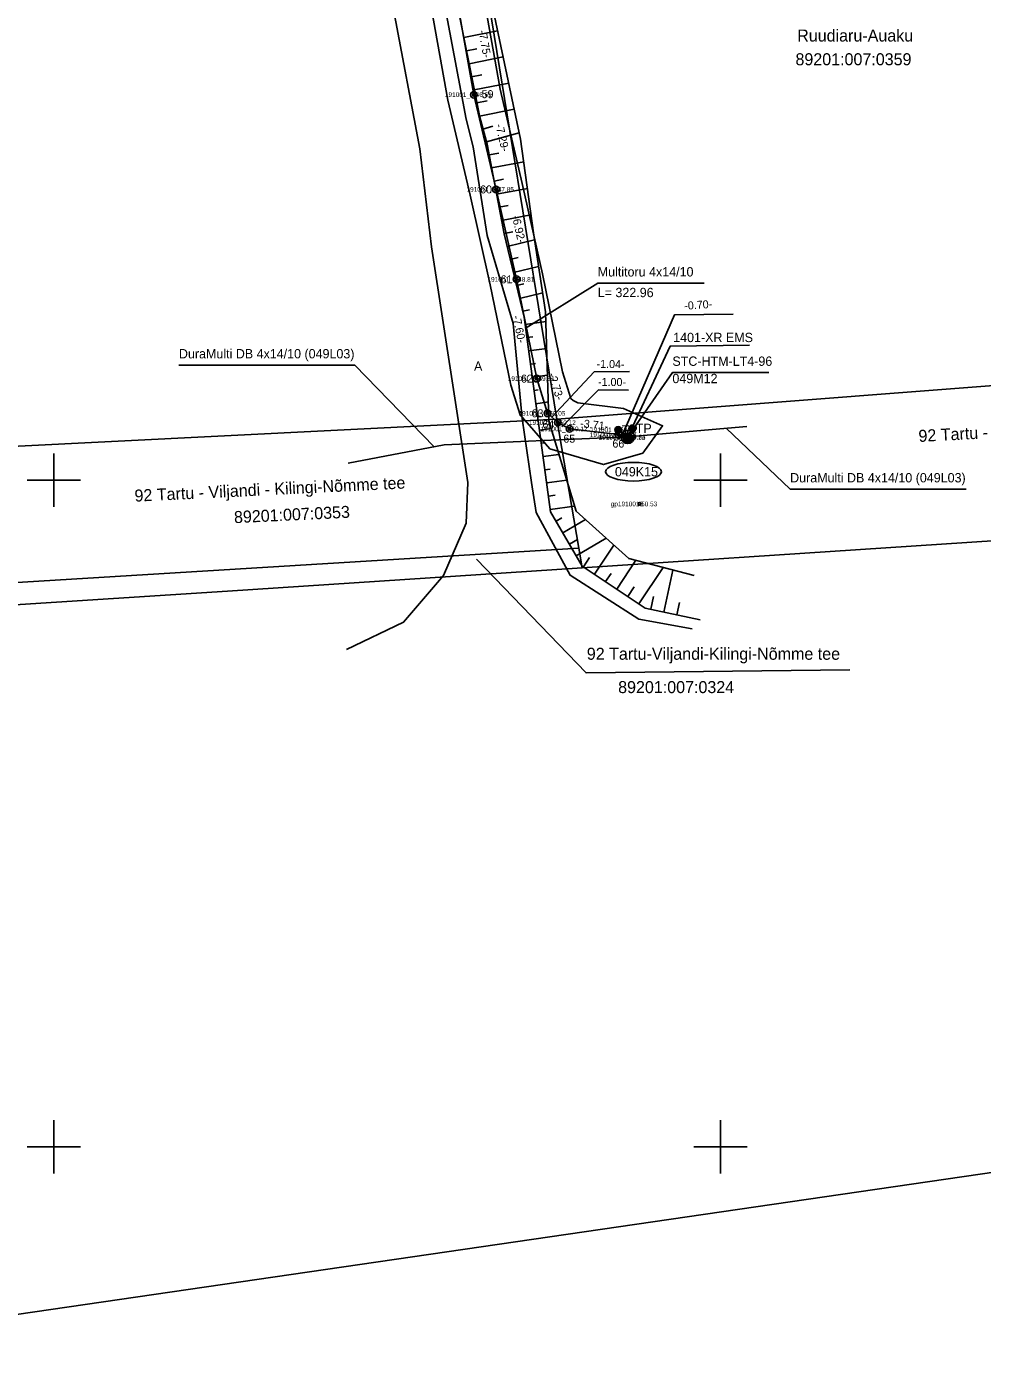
# Model space of a CAD drawing. Extents: x 604066 to 604956, y 6473634 to 6474346.
# Drawn here: x 604648 to 604719.6, y 6473633.8 to 6473734 of the extents above; entities that cross this region are included whole.
import ezdxf

# ---------------------------------------------------------------- set-up
doc = ezdxf.new("R2010")
doc.units = 0
for name, color, linetype in [('ABIJOONIS', 7, 'Continuous'), ('JOONSIDE', 7, 'Continuous'), ('KAEVUNR', 7, 'Continuous'), ('KOORDPUNKT', 7, 'Continuous'), ('MOOTKORG', 7, 'Continuous'), ('MOOTMPUNKT', 7, 'Continuous'), ('MOOTNR', 7, 'Continuous'), ('MOOTPIIR', 7, 'Continuous'), ('PIIR', 7, 'Continuous'), ('POST', 7, 'Continuous'), ('RELJEEF', 7, 'Continuous'), ('SIKAEV', 7, 'Continuous'), ('SITRASS', 7, 'Continuous'), ('TEE', 7, 'Continuous'), ('VORK', 7, 'Continuous'), ('VORMISTUS', 7, 'Continuous')]:
    doc.layers.add(name, color=color, linetype=linetype)

msp = doc.modelspace()

# ---------------------------------------------------------------- linework, layer by layer
at = {"layer": 'ABIJOONIS'}
msp.add_ellipse((604693.47, 6473700.63), major_axis=(2.1, 0), ratio=0.333333, dxfattribs=at)
at = {"layer": 'JOONSIDE'}
for points in [[(604692.63, 6473703.34), (604696.55, 6473712.4), (604700.95, 6473712.45)], [(604687.31, 6473704.69), (604690.51, 6473708.12), (604693.17, 6473708.14)], [(604688.09, 6473703.99), (604690.85, 6473706.78), (604693.09, 6473706.75)]]:
    msp.add_lwpolyline(points, dxfattribs=at)
at = {"layer": 'KOORDPUNKT'}
for centre, radius in [((604681.5, 6473728.9), 0.25), ((604681.5, 6473728.9), 0.025), ((604681.5, 6473728.9), 0.0221), ((604681.5, 6473728.9), 0.0161), ((604681.5, 6473728.9), 0.0191), ((604681.5, 6473728.9), 0.0132), ((604681.5, 6473728.9), 0.00726), ((604681.5, 6473728.9), 0.0102), ((604681.5, 6473728.9), 0.0043), ((604683.16, 6473721.8), 0.25), ((604683.16, 6473721.8), 0.025), ((604683.16, 6473721.8), 0.0221), ((604683.16, 6473721.8), 0.0161), ((604683.16, 6473721.8), 0.0191), ((604683.16, 6473721.8), 0.0132), ((604683.16, 6473721.8), 0.0043), ((604683.16, 6473721.8), 0.00726), ((604683.16, 6473721.8), 0.0102), ((604684.69, 6473715.06), 0.25), ((604684.69, 6473715.06), 0.025), ((604684.69, 6473715.06), 0.0191), ((604684.69, 6473715.06), 0.0221), ((604684.69, 6473715.06), 0.0161), ((604684.69, 6473715.06), 0.00726), ((604684.69, 6473715.06), 0.0102), ((604684.69, 6473715.06), 0.0132), ((604684.69, 6473715.06), 0.0043), ((604686.21, 6473707.61), 0.25), ((604686.21, 6473707.61), 0.025), ((604686.21, 6473707.61), 0.0161), ((604686.21, 6473707.61), 0.0191), ((604686.21, 6473707.61), 0.0221), ((604686.21, 6473707.61), 0.0132), ((604686.21, 6473707.61), 0.0043), ((604686.21, 6473707.61), 0.00726), ((604686.21, 6473707.61), 0.0102), ((604687.02, 6473705.01), 0.25), ((604687.02, 6473705.01), 0.025), ((604687.02, 6473705.01), 0.0161), ((604687.02, 6473705.01), 0.0191), ((604687.02, 6473705.01), 0.0221), ((604687.02, 6473705.01), 0.00726), ((604687.02, 6473705.01), 0.0102), ((604687.02, 6473705.01), 0.0132), ((604687.02, 6473705.01), 0.0043), ((604687.8, 6473704.32), 0.25), ((604687.8, 6473704.32), 0.0221), ((604687.8, 6473704.32), 0.025), ((604687.8, 6473704.32), 0.0191), ((604687.8, 6473704.32), 0.0132), ((604687.8, 6473704.32), 0.0161), ((604687.8, 6473704.32), 0.0102), ((604687.8, 6473704.32), 0.0043), ((604687.8, 6473704.32), 0.00726), ((604688.68, 6473703.84), 0.25), ((604688.68, 6473703.84), 0.0221), ((604688.68, 6473703.84), 0.025), ((604688.68, 6473703.84), 0.0132), ((604688.68, 6473703.84), 0.0161), ((604688.68, 6473703.84), 0.0191), ((604688.68, 6473703.84), 0.0102), ((604688.68, 6473703.84), 0.0043), ((604688.68, 6473703.84), 0.00726), ((604692.36, 6473703.41), 0.25), ((604692.36, 6473703.41), 0.0191), ((604692.36, 6473703.41), 0.0221), ((604692.36, 6473703.41), 0.025), ((604692.36, 6473703.41), 0.0102), ((604692.36, 6473703.41), 0.0132), ((604692.36, 6473703.41), 0.0161), ((604692.36, 6473703.41), 0.0043), ((604692.36, 6473703.41), 0.00726), ((604693.04, 6473703.24), 0.25), ((604693.04, 6473703.24), 0.025), ((604693.04, 6473703.24), 0.0191), ((604693.04, 6473703.24), 0.0221), ((604693.04, 6473703.24), 0.0161), ((604693.04, 6473703.24), 0.00726), ((604693.04, 6473703.24), 0.0102), ((604693.04, 6473703.24), 0.0132), ((604693.04, 6473703.24), 0.0043)]:
    msp.add_circle(centre, radius, dxfattribs=at)
at = {"layer": 'MOOTMPUNKT'}
for centre in [(604681.5, 6473728.9), (604683.16, 6473721.8), (604684.69, 6473715.06), (604686.21, 6473707.61), (604687.02, 6473705.01), (604687.8, 6473704.32), (604688.68, 6473703.84), (604692.33, 6473703.77), (604692.36, 6473703.41), (604693.04, 6473703.24), (604693.91, 6473698.22)]:
    msp.add_circle(centre, 0.1, dxfattribs=at)
at = {"layer": 'MOOTPIIR'}
msp.add_lwpolyline([(604678.17, 6473736.19), (604679.54, 6473728.5), (604681.21, 6473721.36), (604682.73, 6473714.64), (604684.27, 6473707.11), (604684.96, 6473704.89), (604687.2, 6473702.34), (604691.21, 6473701.16), (604694.16, 6473702.01), (604695.65, 6473704.08), (604692.72, 6473705.38), (604689.29, 6473705.79), (604688.95, 6473705.97), (604688.76, 6473706.13), (604688.15, 6473708.11), (604686.64, 6473715.48), (604685.11, 6473722.25), (604683.46, 6473729.31), (604682.11, 6473736.88)], dxfattribs=at)
at = {"layer": 'PIIR'}
for points in [[(604833.54, 6473909.5), (604897.39, 6473936.49), (604953.49, 6473960.24), (604956.07, 6473961.29), (604940.8, 6473724.06), (604687.73, 6473704.56), (604680.66, 6473747.8), (604821.94, 6473844.68)], [(604687.73, 6473704.56), (604940.8, 6473724.06), (604940.18, 6473714.53), (604940.07, 6473712.83), (604892.72, 6473708.69), (604839.74, 6473704.2), (604787.09, 6473700.12), (604735.18, 6473696.42), (604689.63, 6473693.43), (604689.38, 6473694.91)], [(604429.15, 6473679), (604428.82, 6473685.17), (604422.99, 6473691.29), (604687.73, 6473704.56), (604689.38, 6473694.91)], [(604429.15, 6473679), (604689.38, 6473694.91), (604689.63, 6473693.43), (604663.03, 6473691.68), (604611.7, 6473688.38), (604559, 6473685.22), (604513.61, 6473682.6), (604464, 6473679.51), (604429.23, 6473677.5)]]:
    msp.add_lwpolyline(points, close=True, dxfattribs=at)
for points in [[(604392.23, 6473874.61), (604414.7, 6473872.41), (604426.55, 6473871.03), (604444.65, 6473869.66), (604482.63, 6473866.81), (604486.98, 6473866.41), (604549.55, 6473854.82), (604575.16, 6473852.02), (604645.55, 6473867.92), (604659, 6473875.69), (604714.62, 6473889.17), (604776, 6473903.81), (604824.84, 6473905.94), (604833.54, 6473909.5), (604821.94, 6473844.68), (604680.66, 6473747.8), (604687.73, 6473704.56), (604422.99, 6473691.29), (604421.99, 6473694.09), (604395.15, 6473723.9)], [(604681.7, 6473694.08), (604689.92, 6473685.54), (604709.7, 6473685.77)]]:
    msp.add_lwpolyline(points, dxfattribs=at)
at = {"layer": 'POST'}
for centre, radius in [((604692.33, 6473703.77), 0.25), ((604692.33, 6473703.77), 0.225), ((604692.33, 6473703.77), 0.2), ((604693.38, 6473703.88), 0.25), ((604693.38, 6473703.88), 0.225), ((604693.38, 6473703.88), 0.2), ((604693.38, 6473703.88), 0.175), ((604693.38, 6473703.88), 0.15), ((604693.38, 6473703.88), 0.125), ((604693.38, 6473703.88), 0.1), ((604693.38, 6473703.88), 0.075), ((604692.33, 6473703.77), 0.175), ((604692.33, 6473703.77), 0.15), ((604692.33, 6473703.77), 0.125), ((604692.33, 6473703.77), 0.1), ((604692.33, 6473703.77), 0.075), ((604692.33, 6473703.77), 0.05), ((604692.33, 6473703.77), 0.025), ((604693.38, 6473703.88), 0.05), ((604693.38, 6473703.88), 0.025)]:
    msp.add_circle(centre, radius, dxfattribs=at)
at = {"layer": 'RELJEEF'}
for p, q in [((604680.75, 6473733.18), (604683.28, 6473733.69)), ((604680.94, 6473732.2), (604681.71, 6473732.35)), ((604681.14, 6473731.22), (604683.7, 6473731.73)), ((604681.33, 6473730.24), (604682.1, 6473730.39)), ((604681.53, 6473729.26), (604684.11, 6473729.77)), ((604681.72, 6473728.28), (604682.5, 6473728.43)), ((604681.92, 6473727.3), (604684.53, 6473727.82)), ((604682.18, 6473726.33), (604682.93, 6473726.54)), ((604682.44, 6473725.37), (604684.9, 6473726.04)), ((604682.64, 6473724.39), (604683.38, 6473724.53)), ((604682.83, 6473723.41), (604685.24, 6473723.86)), ((604683.02, 6473722.42), (604683.72, 6473722.56)), ((604683.2, 6473721.44), (604685.51, 6473721.88)), ((604683.39, 6473720.46), (604684.06, 6473720.59)), ((604683.58, 6473719.48), (604685.78, 6473719.9)), ((604683.76, 6473718.49), (604684.41, 6473718.62)), ((604684, 6473717.52), (604686.04, 6473718.01)), ((604684.23, 6473716.55), (604684.82, 6473716.69)), ((604684.46, 6473715.58), (604686.35, 6473716.03)), ((604684.7, 6473714.6), (604685.24, 6473714.73)), ((604684.93, 6473713.63), (604686.66, 6473714.05)), ((604685.16, 6473712.66), (604685.66, 6473712.78)), ((604685.34, 6473711.68), (604686.91, 6473711.89)), ((604685.48, 6473710.69), (604685.91, 6473710.75)), ((604685.61, 6473709.69), (604686.97, 6473709.88)), ((604685.75, 6473708.7), (604686.12, 6473708.75)), ((604685.88, 6473707.71), (604687.03, 6473707.87)), ((604686.01, 6473706.72), (604686.33, 6473706.76)), ((604686.15, 6473705.73), (604687.09, 6473705.86)), ((604686.28, 6473704.74), (604686.53, 6473704.77)), ((604686.42, 6473703.75), (604687.3, 6473703.87)), ((604686.55, 6473702.76), (604686.86, 6473702.8)), ((604686.69, 6473701.77), (604687.88, 6473701.93)), ((604686.82, 6473700.78), (604687.23, 6473700.83)), ((604686.96, 6473699.79), (604688.46, 6473699.99)), ((604687.09, 6473698.8), (604687.59, 6473698.86)), ((604687.23, 6473697.8), (604689.04, 6473698.05)), ((604687.67, 6473696.92), (604688.1, 6473697.17)), ((604688.17, 6473696.05), (604689.86, 6473697.04)), ((604688.67, 6473695.19), (604689.27, 6473695.54)), ((604689.18, 6473694.33), (604691.43, 6473695.64)), ((604690.55, 6473692.94), (604692, 6473695.13)), ((604689.71, 6473693.49), (604690.17, 6473694.19)), ((604692.21, 6473691.83), (604693.65, 6473693.99)), ((604691.38, 6473692.39), (604691.79, 6473693.01)), ((604693.88, 6473690.73), (604695.69, 6473693.46)), ((604695.75, 6473690.11), (604696.43, 6473693.26)), ((604693.04, 6473691.28), (604693.53, 6473692.01)), ((604694.77, 6473690.32), (604694.98, 6473691.28)), ((604696.73, 6473689.9), (604696.93, 6473690.83))]:
    msp.add_line(p, q, dxfattribs=at)
for points in [[(604672.96, 6473774.44), (604673.75, 6473769.08), (604676.06, 6473758.37), (604677.74, 6473747.48), (604680.01, 6473736.85), (604681.94, 6473727.21), (604682.49, 6473725.19), (604683.77, 6473718.46), (604685.27, 6473712.22), (604687.25, 6473697.63), (604689.63, 6473693.55), (604694.35, 6473690.41), (604698.46, 6473689.52)], [(604674.27, 6473774.8), (604675.61, 6473769.86), (604677.36, 6473758.59), (604680.19, 6473748.09), (604682.49, 6473737.41), (604685, 6473725.57), (604685.96, 6473718.55), (604686.88, 6473712.63), (604687.13, 6473704.44), (604689.16, 6473697.67), (604693.13, 6473694.13), (604698.02, 6473692.84)]]:
    msp.add_lwpolyline(points, dxfattribs=at)
at = {"layer": 'SIKAEV'}
for p, q in [((604693.04, 6473703.24), (604692.62, 6473702.96)), ((604693.04, 6473703.74), (604693.04, 6473703.24)), ((604693.04, 6473703.24), (604693.45, 6473702.96))]:
    msp.add_line(p, q, dxfattribs=at)
msp.add_circle((604693.04, 6473703.24), 0.5, dxfattribs=at)
for radius in [0.475, 0.45, 0.425, 0.4, 0.375, 0.35, 0.325, 0.3, 0.275, 0.25, 0.225, 0.2, 0.175, 0.15, 0.125, 0.1, 0.075, 0.05]:
    msp.add_arc((604693.04, 6473703.24), radius, 213.5305, 326.4695, dxfattribs=at)
at = {"layer": 'SITRASS'}
for p, q in [((604693.04, 6473703.24), (604701.98, 6473704.02)), ((604692.45, 6473703.29), (604693.06, 6473703.51)), ((604692.45, 6473703.29), (604693.02, 6473702.97)), ((604692.45, 6473703.29), (604692.45, 6473703.29)), ((604692.48, 6473703.27), (604692.47, 6473703.3)), ((604692.52, 6473703.25), (604692.5, 6473703.3)), ((604692.56, 6473703.23), (604692.52, 6473703.31)), ((604692.59, 6473703.21), (604692.54, 6473703.32)), ((604692.79, 6473703.24), (604692.54, 6473703.24)), ((604692.63, 6473703.19), (604692.57, 6473703.33)), ((604692.66, 6473703.17), (604692.59, 6473703.34)), ((604692.7, 6473703.15), (604692.61, 6473703.35)), ((604692.73, 6473703.13), (604692.64, 6473703.36)), ((604692.77, 6473703.11), (604692.66, 6473703.36)), ((604692.8, 6473703.09), (604692.68, 6473703.37)), ((604692.86, 6473703.41), (604692.69, 6473703.59)), ((604692.86, 6473703.06), (604692.69, 6473702.88)), ((604692.84, 6473703.07), (604692.71, 6473703.38)), ((604692.87, 6473703.05), (604692.73, 6473703.39)), ((604692.91, 6473703.03), (604692.75, 6473703.4)), ((604692.95, 6473703.01), (604692.78, 6473703.41)), ((604692.98, 6473702.99), (604692.8, 6473703.42)), ((604693.02, 6473702.97), (604692.82, 6473703.43)), ((604693.04, 6473702.98), (604692.85, 6473703.43)), ((604693.06, 6473702.99), (604692.87, 6473703.44)), ((604693.09, 6473703), (604692.9, 6473703.45)), ((604693.11, 6473703), (604692.92, 6473703.46)), ((604693.13, 6473703.01), (604692.94, 6473703.47)), ((604693.16, 6473703.02), (604692.97, 6473703.48)), ((604693.18, 6473703.03), (604692.99, 6473703.49)), ((604693.21, 6473703.04), (604693.01, 6473703.49)), ((604693.63, 6473703.19), (604693.02, 6473702.97)), ((604693.04, 6473703.49), (604693.04, 6473703.74)), ((604693.23, 6473703.05), (604693.04, 6473703.5)), ((604693.04, 6473702.99), (604693.04, 6473702.74)), ((604693.63, 6473703.19), (604693.06, 6473703.51)), ((604693.25, 6473703.06), (604693.06, 6473703.51)), ((604693.28, 6473703.06), (604693.09, 6473703.49)), ((604693.3, 6473703.07), (604693.13, 6473703.47)), ((604693.32, 6473703.08), (604693.17, 6473703.45)), ((604693.35, 6473703.09), (604693.2, 6473703.43)), ((604693.22, 6473703.41), (604693.39, 6473703.59)), ((604693.22, 6473703.06), (604693.39, 6473702.88)), ((604693.37, 6473703.1), (604693.24, 6473703.41)), ((604693.39, 6473703.11), (604693.27, 6473703.39)), ((604693.29, 6473703.24), (604693.54, 6473703.24)), ((604693.42, 6473703.12), (604693.31, 6473703.37)), ((604693.44, 6473703.12), (604693.34, 6473703.35)), ((604693.46, 6473703.13), (604693.38, 6473703.34)), ((604693.49, 6473703.14), (604693.41, 6473703.32)), ((604693.51, 6473703.15), (604693.45, 6473703.3)), ((604693.53, 6473703.16), (604693.48, 6473703.28)), ((604693.56, 6473703.17), (604693.52, 6473703.26)), ((604693.58, 6473703.18), (604693.56, 6473703.24)), ((604693.6, 6473703.18), (604693.59, 6473703.22))]:
    msp.add_line(p, q, dxfattribs=at)
for points in [[(604680.14, 6473736.53), (604681.5, 6473728.9), (604683.16, 6473721.8), (604684.69, 6473715.06), (604686.21, 6473707.61), (604687.02, 6473705.01), (604687.8, 6473704.32), (604688.68, 6473703.84), (604692.36, 6473703.41), (604693.04, 6473703.24)], [(604685.43, 6473711.43), (604690.79, 6473714.77), (604698.77, 6473714.77)], [(604693.04, 6473703.24), (604696.21, 6473710.04), (604702.17, 6473710.13)], [(604678.51, 6473702.5), (604672.57, 6473708.63), (604659.38, 6473708.63)], [(604693.04, 6473703.24), (604696.39, 6473708.07), (604703.63, 6473708.07)], [(604693.04, 6473703.24), (604679.26, 6473702.64), (604672.06, 6473701.27)], [(604700.43, 6473703.89), (604705.22, 6473699.33), (604718.41, 6473699.33)]]:
    msp.add_lwpolyline(points, dxfattribs=at)
for radius in [0.25, 0.225, 0.2, 0.175, 0.15, 0.125, 0.1, 0.075, 0.05, 0.025]:
    msp.add_circle((604693.04, 6473703.24), radius, dxfattribs=at)
at = {"layer": 'TEE'}
for points in [[(604658.81, 6473832.59), (604663.41, 6473815.74), (604666.28, 6473803.94), (604668.26, 6473793.28), (604670.52, 6473784.17), (604671.08, 6473780.07), (604671.45, 6473778.51), (604672.22, 6473774.12), (604673.16, 6473768.83), (604674.71, 6473758.23), (604677.04, 6473747.39), (604679.12, 6473736.65), (604680.92, 6473727.06), (604681.45, 6473725), (604682.5, 6473718.34), (604684.44, 6473711.75), (604685.12, 6473704.62), (604685.81, 6473699.83), (604686.18, 6473697.57), (604688.71, 6473692.87), (604693.86, 6473689.57), (604697.87, 6473688.86)], [(604654.6, 6473831.66), (604658.7, 6473815.39), (604661.34, 6473804.07), (604663.57, 6473792.58), (604666.57, 6473778.33), (604668.53, 6473769.38), (604671.17, 6473757.48), (604673.52, 6473745.14), (604675.48, 6473735.29), (604677.45, 6473724.84), (604678.32, 6473717.49), (604681.05, 6473699.83), (604680.92, 6473696.77), (604679.22, 6473692.84), (604676.23, 6473689.35), (604671.94, 6473687.31)]]:
    msp.add_lwpolyline(points, dxfattribs=at)
at = {"layer": 'VORK'}
for p, q in [((604650, 6473702), (604650, 6473698)), ((604700, 6473702), (604700, 6473698)), ((604648, 6473700), (604652, 6473700)), ((604698, 6473700), (604702, 6473700)), ((604650, 6473652), (604650, 6473648)), ((604700, 6473652), (604700, 6473648)), ((604648, 6473650), (604652, 6473650)), ((604698, 6473650), (604702, 6473650))]:
    msp.add_line(p, q, dxfattribs=at)
at = {"layer": 'VORMISTUS'}
msp.add_lwpolyline([(604563.86, 6474037.6), (604705.86, 6474058.26), (604764.62, 6473654.52), (604622.61, 6473633.85)], close=True, dxfattribs=at)

# ---------------------------------------------------------------- texts
at = {"layer": 'JOONSIDE'}
for s, rotation, p in [('-7.75-', 280.1005, (604681.85, 6473733.69)), ('-7.29-', 283.1537, (604683.11, 6473726.64)), ('-6.92-', 282.7786, (604684.35, 6473719.78)), ('-0.70-', 3.9591, (604697.3, 6473712.77)), ('-7.60-', 281.5376, (604684.4, 6473712.29)), ('-1.04-', 359.2568, (604690.7, 6473708.42)), ('-2.73-', 287.3051, (604687.07, 6473707.94)), ('-1.00-', 359.4668, (604690.81, 6473707.07)), ('-3.71-', 353.2289, (604689.45, 6473703.98))]:
    msp.add_text(s, height=0.6, rotation=rotation, dxfattribs=at).set_placement(p)
at = {"layer": 'KAEVUNR'}
msp.add_text('049K15', height=0.7, dxfattribs=at).set_placement((604692.08, 6473700.28))
at = {"layer": 'KOORDPUNKT'}
for s, p in [('59 ', (604682.08, 6473728.64)), ('60 ', (604681.97, 6473721.5)), ('61 ', (604683.5, 6473714.76)), ('62 ', (604685.03, 6473707.31)), ('63 ', (604685.83, 6473704.71)), ('64 ', (604686.64, 6473703.89)), ('65 ', (604688.21, 6473702.81)), ('66 ', (604691.89, 6473702.44))]:
    msp.add_text(s, height=0.6, dxfattribs=at).set_placement(p)
at = {"layer": 'MOOTKORG'}
for s, p in [(' 46.61', (604681.5, 6473728.73)), (' 47.85', (604683.16, 6473721.63)), (' 48.81', (604684.69, 6473714.88)), (' 49.81', (604686.21, 6473707.44)), (' 50.05', (604687.02, 6473704.83)), (' 50.12', (604687.8, 6473704.14)), (' 50.12', (604688.68, 6473703.67)), (' 50.05', (604692.33, 6473703.6)), (' 49.37', (604692.36, 6473703.23)), (' 49.22', (604693.02, 6473703.04)), (' 49.64', (604693.04, 6473703.06)), (' 50.53', (604693.91, 6473698.04))]:
    msp.add_text(s, height=0.35, dxfattribs=at).set_placement(p)
at = {"layer": 'MOOTNR'}
for s, p in [('191001_63 ', (604679.33, 6473728.73)), ('191001_64 ', (604680.95, 6473721.63)), ('191001_65 ', (604682.52, 6473714.88)), ('191001_66 ', (604684.04, 6473707.44)), ('191001_67 ', (604684.85, 6473704.83)), ('191001_68 ', (604685.63, 6473704.14)), ('191001_69 ', (604686.51, 6473703.67)), ('191001_71 ', (604690.23, 6473703.6)), ('191001_70 ', (604690.19, 6473703.23)), ('191001_73 ', (604690.85, 6473703.04)), ('191001_72 ', (604690.87, 6473703.06)), ('gp1910013 ', (604691.77, 6473698.04))]:
    msp.add_text(s, height=0.35, dxfattribs=at).set_placement(p)
at = {"layer": 'PIIR'}
for s, p in [('Ruudiaru-Auaku', (604705.75, 6473732.89)), ('89201:007:0359', (604705.62, 6473731.11)), ('92 Tartu-Viljandi-Kilingi-Nõmme tee', (604689.97, 6473686.53)), ('89201:007:0324', (604692.32, 6473684.03))]:
    msp.add_text(s, height=0.9, dxfattribs=at).set_placement(p)
for s, rotation, p in [('92 Tartu - Viljandi - Kilingi-Nõmme tee', 3.0938, (604714.87, 6473702.86)), ('92 Tartu - Viljandi - Kilingi-Nõmme tee', 2.8023, (604656.07, 6473698.38)), ('89201:007:0353', 2.712, (604663.53, 6473696.77))]:
    msp.add_text(s, height=0.9, rotation=rotation, dxfattribs=at).set_placement(p)
at = {"layer": 'POST'}
for p in [(604692.33, 6473703.42), (604693.38, 6473703.53)]:
    msp.add_text(' TP', height=0.7, dxfattribs=at).set_placement(p)
at = {"layer": 'SITRASS'}
for s, p in [('Multitoru 4x14/10 ', (604690.79, 6473715.27)), ('L= 322.96', (604690.79, 6473713.72)), ('1401-XR EMS', (604696.45, 6473710.35)), ('DuraMulti DB 4x14/10 (049L03)', (604659.38, 6473709.13)), ('STC-HTM-LT4-96', (604696.39, 6473708.57)), ('049M12', (604696.39, 6473707.27)), ('DuraMulti DB 4x14/10 (049L03)', (604705.22, 6473699.83))]:
    msp.add_text(s, height=0.7, dxfattribs=at).set_placement(p)
at = {"layer": 'TEE'}
msp.add_text('A', height=0.7, dxfattribs=at).set_placement((604681.51, 6473708.2))

doc.saveas('drawing.dxf')
